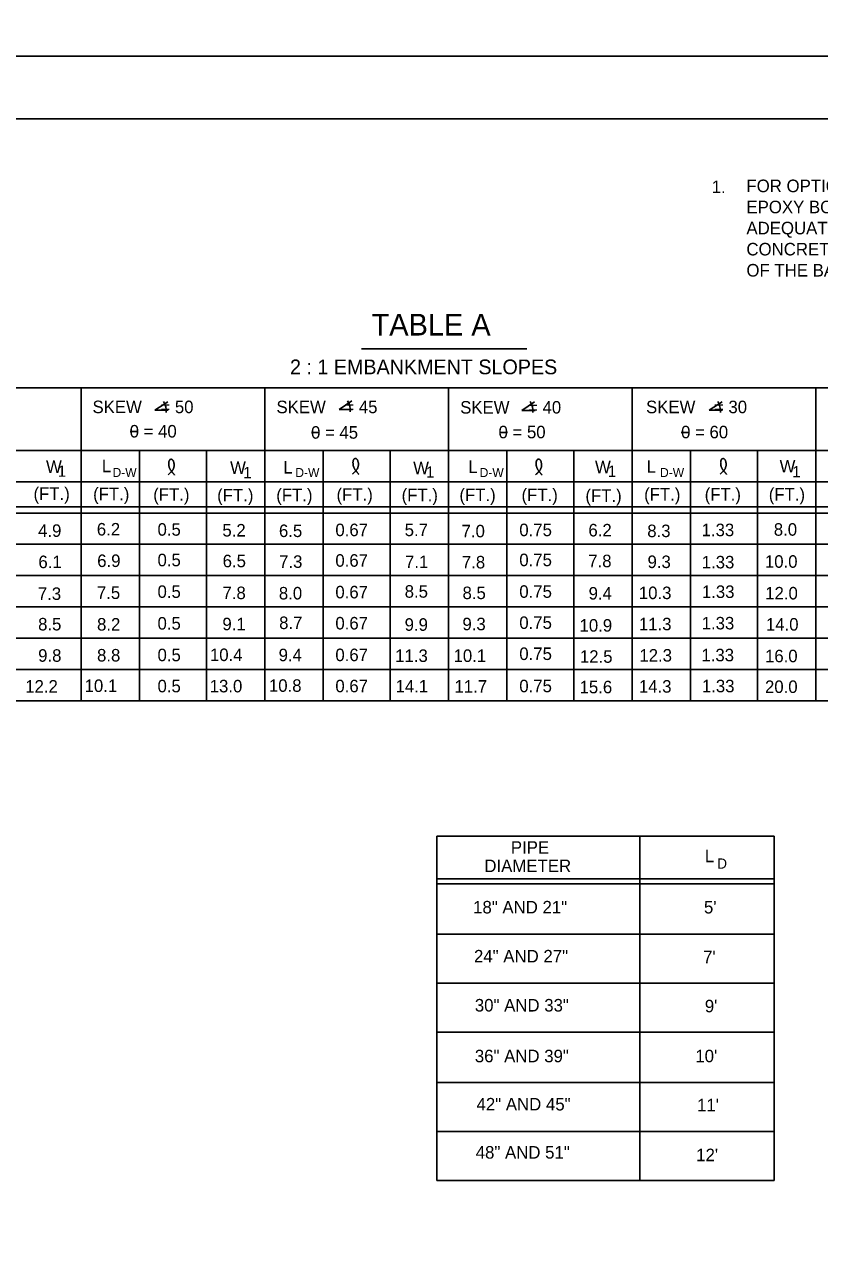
# Model space of a CAD drawing. Extents: x 638877 to 639960, y 297341 to 299123.
# Drawn here: x 639328 to 639517.9, y 297649 to 297942.8 of the extents above; entities that cross this region are included whole.
import ezdxf

# ---------------------------------------------------------------- set-up
doc = ezdxf.new("R2010")
doc.units = 0
for name, color, linetype in [('1', 7, 'Continuous'), ('2', 7, 'Continuous'), ('3', 7, 'Continuous'), ('PLT-BNDY', 7, 'Continuous')]:
    doc.layers.add(name, color=color, linetype=linetype)

msp = doc.modelspace()

# ---------------------------------------------------------------- linework, layer by layer
at = {"layer": '1'}
msp.add_line((639703.19, 297920.28), (638917.19, 297920.28), dxfattribs=at)
at = {"layer": '2'}
for p, q in [((639507.09, 297748.87), (639426.48, 297748.87)), ((639426.48, 297666.64), (639426.48, 297748.87)), ((639475.03, 297666.64), (639475.03, 297748.87)), ((639507.09, 297666.64), (639507.09, 297748.87)), ((639507.09, 297738.71), (639426.48, 297738.71)), ((639507.09, 297737.51), (639426.48, 297737.51)), ((639507.09, 297725.48), (639426.48, 297725.48)), ((639507.09, 297713.78), (639426.48, 297713.78)), ((639507.09, 297702.08), (639426.48, 297702.08)), ((639507.09, 297690.04), (639426.48, 297690.04)), ((639507.09, 297678.34), (639426.48, 297678.34)), ((639507.09, 297666.64), (639426.48, 297666.64))]:
    msp.add_line(p, q, dxfattribs=at)
at = {"layer": '3'}
for p, q in [((639408.47, 297865.33), (639448.03, 297865.33)), ((639233.8, 297856.01), (639632.75, 297856.01)), ((639341.51, 297856.01), (639341.51, 297781.21)), ((639385.4, 297856.01), (639385.4, 297781.21)), ((639429.28, 297856.01), (639429.28, 297781.21)), ((639473.17, 297856.01), (639473.17, 297781.21)), ((639517.05, 297856.01), (639517.05, 297781.21)), ((639359.13, 297850.65), (639362.21, 297852.69)), ((639403.15, 297850.84), (639406.22, 297852.88)), ((639446.79, 297850.62), (639449.86, 297852.66)), ((639491.56, 297850.65), (639494.64, 297852.69)), ((639362.34, 297850.65), (639359.13, 297850.65)), ((639406.35, 297850.84), (639403.15, 297850.84)), ((639449.99, 297850.62), (639446.79, 297850.62)), ((639494.77, 297850.65), (639491.56, 297850.65)), ((639353.21, 297845.58), (639355.15, 297845.58)), ((639396.54, 297845.29), (639398.48, 297845.29)), ((639441.44, 297845.36), (639443.38, 297845.36)), ((639484.91, 297845.36), (639486.85, 297845.36)), ((639233.8, 297841.05), (639632.75, 297841.05)), ((639355.48, 297841.05), (639355.48, 297781.21)), ((639371.44, 297841.05), (639371.44, 297781.21)), ((639399.36, 297841.05), (639399.36, 297781.21)), ((639415.32, 297841.05), (639415.32, 297781.21)), ((639443.25, 297841.05), (639443.25, 297781.21)), ((639459.21, 297841.05), (639459.21, 297781.21)), ((639487.13, 297841.05), (639487.13, 297781.21)), ((639503.09, 297841.05), (639503.09, 297781.21)), ((639233.8, 297833.57), (639632.75, 297833.57)), ((639233.8, 297827.59), (639632.75, 297827.59)), ((639233.8, 297826.09), (639632.75, 297826.09)), ((639233.8, 297818.61), (639632.75, 297818.61)), ((639233.8, 297811.13), (639632.75, 297811.13)), ((639233.8, 297803.65), (639632.75, 297803.65)), ((639233.8, 297796.17), (639632.75, 297796.17)), ((639233.8, 297788.69), (639632.75, 297788.69)), ((639233.8, 297781.21), (639632.75, 297781.21))]:
    msp.add_line(p, q, dxfattribs=at)
for centre in [(639357.76, 297850.51), (639401.77, 297850.7), (639445.41, 297850.48), (639490.19, 297850.51)]:
    msp.add_arc(centre, 4.07, 354.1715, 33.0785, dxfattribs=at)
for points in [[(639362.31, 297835.23), (639362.47, 297835.37), (639362.57, 297835.48), (639362.74, 297835.63), (639362.86, 297835.77), (639363.08, 297835.93), (639363.24, 297836.13), (639363.38, 297836.29), (639363.48, 297836.47), (639363.57, 297836.68), (639363.63, 297836.86), (639363.69, 297837.04), (639363.71, 297837.2), (639363.74, 297837.4), (639363.75, 297837.58), (639363.74, 297837.77), (639363.7, 297837.97), (639363.66, 297838.16), (639363.62, 297838.35), (639363.55, 297838.53), (639363.49, 297838.64), (639363.41, 297838.72), (639363.34, 297838.79), (639363.26, 297838.86), (639363.17, 297838.91), (639363.1, 297838.93), (639362.97, 297838.93), (639362.89, 297838.91), (639362.77, 297838.87), (639362.7, 297838.8), (639362.65, 297838.73), (639362.6, 297838.64), (639362.54, 297838.55), (639362.51, 297838.43), (639362.48, 297838.35), (639362.46, 297838.15), (639362.44, 297838.02), (639362.46, 297837.87), (639362.46, 297837.71), (639362.48, 297837.49), (639362.5, 297837.3), (639362.53, 297837.17), (639362.59, 297836.99), (639362.67, 297836.81), (639362.74, 297836.66), (639362.82, 297836.5), (639362.92, 297836.32), (639363.07, 297836.18), (639363.17, 297836.01), (639363.28, 297835.88), (639363.37, 297835.74), (639363.48, 297835.6), (639363.59, 297835.47), (639363.67, 297835.38), (639363.76, 297835.27), (639363.85, 297835.14)], [(639406.33, 297835.41), (639406.5, 297835.55), (639406.6, 297835.65), (639406.76, 297835.81), (639406.88, 297835.94), (639407.11, 297836.11), (639407.26, 297836.31), (639407.41, 297836.47), (639407.5, 297836.65), (639407.59, 297836.85), (639407.65, 297837.04), (639407.72, 297837.22), (639407.74, 297837.38), (639407.76, 297837.58), (639407.77, 297837.75), (639407.76, 297837.95), (639407.73, 297838.15), (639407.69, 297838.34), (639407.64, 297838.53), (639407.57, 297838.71), (639407.51, 297838.82), (639407.44, 297838.9), (639407.36, 297838.97), (639407.28, 297839.04), (639407.19, 297839.09), (639407.12, 297839.11), (639406.99, 297839.11), (639406.91, 297839.09), (639406.8, 297839.05), (639406.72, 297838.98), (639406.67, 297838.91), (639406.62, 297838.82), (639406.56, 297838.73), (639406.54, 297838.61), (639406.51, 297838.53), (639406.48, 297838.33), (639406.46, 297838.2), (639406.48, 297838.04), (639406.48, 297837.89), (639406.51, 297837.67), (639406.53, 297837.48), (639406.55, 297837.35), (639406.61, 297837.17), (639406.69, 297836.99), (639406.77, 297836.83), (639406.84, 297836.68), (639406.94, 297836.5), (639407.1, 297836.35), (639407.19, 297836.19), (639407.3, 297836.06), (639407.39, 297835.92), (639407.5, 297835.78), (639407.61, 297835.65), (639407.69, 297835.56), (639407.78, 297835.45), (639407.87, 297835.32)], [(639450.09, 297835.25), (639450.25, 297835.39), (639450.35, 297835.49), (639450.52, 297835.65), (639450.64, 297835.78), (639450.86, 297835.95), (639451.02, 297836.15), (639451.16, 297836.31), (639451.26, 297836.49), (639451.35, 297836.69), (639451.41, 297836.88), (639451.47, 297837.06), (639451.49, 297837.22), (639451.52, 297837.42), (639451.53, 297837.59), (639451.52, 297837.79), (639451.48, 297837.99), (639451.44, 297838.18), (639451.4, 297838.37), (639451.33, 297838.55), (639451.27, 297838.66), (639451.19, 297838.74), (639451.12, 297838.81), (639451.04, 297838.88), (639450.95, 297838.93), (639450.88, 297838.95), (639450.75, 297838.95), (639450.67, 297838.93), (639450.55, 297838.89), (639450.48, 297838.82), (639450.43, 297838.75), (639450.38, 297838.66), (639450.32, 297838.57), (639450.29, 297838.45), (639450.26, 297838.37), (639450.24, 297838.17), (639450.22, 297838.04), (639450.24, 297837.88), (639450.24, 297837.73), (639450.26, 297837.51), (639450.28, 297837.32), (639450.31, 297837.19), (639450.37, 297837.01), (639450.45, 297836.83), (639450.53, 297836.67), (639450.6, 297836.52), (639450.7, 297836.34), (639450.85, 297836.19), (639450.95, 297836.03), (639451.06, 297835.9), (639451.15, 297835.76), (639451.26, 297835.62), (639451.37, 297835.48), (639451.45, 297835.4), (639451.54, 297835.29), (639451.63, 297835.16)], [(639494.19, 297835.4), (639494.35, 297835.54), (639494.45, 297835.64), (639494.61, 297835.8), (639494.73, 297835.93), (639494.96, 297836.1), (639495.12, 297836.3), (639495.26, 297836.46), (639495.35, 297836.64), (639495.44, 297836.84), (639495.5, 297837.03), (639495.57, 297837.21), (639495.59, 297837.36), (639495.62, 297837.57), (639495.63, 297837.74), (639495.62, 297837.93), (639495.58, 297838.14), (639495.54, 297838.33), (639495.49, 297838.51), (639495.42, 297838.7), (639495.36, 297838.8), (639495.29, 297838.88), (639495.21, 297838.96), (639495.13, 297839.03), (639495.05, 297839.07), (639494.98, 297839.09), (639494.84, 297839.09), (639494.77, 297839.07), (639494.65, 297839.03), (639494.57, 297838.97), (639494.52, 297838.9), (639494.47, 297838.8), (639494.42, 297838.71), (639494.39, 297838.6), (639494.36, 297838.51), (639494.33, 297838.32), (639494.31, 297838.19), (639494.33, 297838.03), (639494.33, 297837.87), (639494.36, 297837.65), (639494.38, 297837.47), (639494.41, 297837.33), (639494.47, 297837.16), (639494.54, 297836.98), (639494.62, 297836.82), (639494.7, 297836.67), (639494.79, 297836.48), (639494.95, 297836.34), (639495.05, 297836.17), (639495.15, 297836.05), (639495.24, 297835.9), (639495.35, 297835.77), (639495.46, 297835.63), (639495.55, 297835.55), (639495.63, 297835.44), (639495.72, 297835.3)]]:
    msp.add_spline(points, degree=3, dxfattribs=at)
at = {"layer": 'PLT-BNDY'}
for points in [[(638877.19, 298529.28), (639718.19, 298529.28), (639718.19, 297935.28), (638877.19, 297935.28)], [(638877.19, 297935.28), (639718.19, 297935.28), (639718.19, 297341.28), (638877.19, 297341.28)]]:
    msp.add_lwpolyline(points, close=True, dxfattribs=at)

# ---------------------------------------------------------------- texts
at = {"layer": '1'}
for s, height, p in [('FOR OPTIONAL CONSTRUCTION JOINT WITHOUT A DEPRESSED KEY, APPLY ', 3, (639500.47, 297902.75)), ('EPOXY BONDING COMPOUND AT THE LOCATION INDICATED TO ENSURE ', 3, (639500.47, 297897.71)), ('ADEQUATE BOND WITH THE BASE SECTION OF THE ENDWALL (NEW ', 3, (639500.47, 297892.67)), ('CONCRETE). CAST THE HEADWALL SECTION OF THE ENDWALL ON TOP ', 3, (639500.47, 297887.63)), ('OF THE BASE SECTION OF THE ENDWALL.', 3, (639500.47, 297882.59)), ('D-W', 2.154, (639349.02, 297834.71)), ('D-W', 2.154, (639392.69, 297834.68)), ('D-W', 2.154, (639436.73, 297834.68)), ('D-W', 2.154, (639479.83, 297834.69)), ('D', 2.43, (639493.49, 297741.13)), ('18" AND 21"', 3, (639435.17, 297730.42)), ("5'", 3, (639490.32, 297730.42)), ('24" AND 27"', 3, (639435.38, 297718.71)), ("7'", 3, (639490.11, 297718.5)), ('30" AND 33"', 3, (639435.58, 297706.99)), ("9'", 3, (639490.53, 297706.79)), ('36" AND 39"', 3, (639435.58, 297694.86)), ("10'", 3, (639488.26, 297694.86)), ('42" AND 45"', 3, (639435.99, 297683.35)), ("11'", 3, (639488.68, 297683.15)), ('48" AND 51"', 3, (639435.79, 297671.84)), ("12'", 3, (639488.47, 297671.23))]:
    msp.add_text(s, height=height, dxfattribs=at).set_placement(p)
at = {"layer": '3'}
for s, height, p in [('1.  ', 3, (639492.17, 297902.52)), ('TABLE A', 5.172, (639410.91, 297868.5)), ('2 : 1 EMBANKMENT SLOPES', 3.5207, (639391.43, 297859.24)), ('SKEW    = 50', 2.9921, (639344.24, 297849.95)), ('SKEW    = 45', 2.9921, (639388.19, 297849.94)), ('SKEW    = 40', 2.9921, (639432.08, 297849.85)), ('SKEW    = 30', 2.9921, (639476.49, 297849.94)), ('0 = 40', 2.992, (639353.12, 297844.13)), ('0 = 45', 2.992, (639396.45, 297843.85)), ('0 = 50', 2.992, (639441.25, 297843.94)), ('0 = 60', 2.992, (639484.86, 297843.94)), ('W', 2.99, (639333.13, 297835.67)), ('1', 2.7, (639335.92, 297834.74)), ('L', 2.99, (639346.47, 297835.85)), ('W', 2.99, (639377.11, 297835.45)), ('1', 2.7, (639380.24, 297834.4)), ('L', 2.99, (639389.83, 297835.53)), ('W', 2.99, (639420.85, 297835.37)), ('1', 2.7, (639423.92, 297834.56)), ('L', 2.99, (639434.01, 297835.67)), ('W', 2.99, (639464.29, 297835.59)), ('1', 2.7, (639467.35, 297834.73)), ('L', 2.99, (639476.63, 297835.71)), ('W', 2.99, (639508.4, 297835.78)), ('1', 2.7, (639511.42, 297834.61)), ('(FT.)', 2.992, (639330.14, 297829.22)), ('(FT.)', 2.992, (639344.38, 297829.14)), ('(FT.)', 2.992, (639358.74, 297829.02)), ('(FT.)', 2.992, (639374.02, 297828.87)), ('(FT.)', 2.992, (639388.14, 297828.89)), ('(FT.)', 2.992, (639402.54, 297829.02)), ('(FT.)', 2.992, (639418.09, 297828.89)), ('(FT.)', 2.992, (639431.9, 297828.93)), ('(FT.)', 2.992, (639446.74, 297828.93)), ('(FT.)', 2.992, (639462, 297828.76)), ('(FT.)', 2.992, (639476.03, 297829.05)), ('(FT.)', 2.992, (639490.49, 297829.05)), ('(FT.)', 2.992, (639505.81, 297829.05)), ('4.9', 2.992, (639331.24, 297820.39)), ('6.2', 2.992, (639345.27, 297820.72)), ('0.5', 2.992, (639359.77, 297820.67)), ('5.2', 2.992, (639375.27, 297820.48)), ('6.5', 2.992, (639388.78, 297820.35)), ('0.67', 2.992, (639402.26, 297820.56)), ('5.7', 2.992, (639418.82, 297820.57)), ('7.0', 2.992, (639432.42, 297820.28)), ('0.75', 2.992, (639446.21, 297820.56)), ('6.2', 2.992, (639462.72, 297820.5)), ('8.3', 2.992, (639476.78, 297820.33)), ('1.33', 2.992, (639489.76, 297820.56)), ('8.0', 2.992, (639507.01, 297820.67)), ('6.9', 2.992, (639345.36, 297813.19)), ('0.5', 2.992, (639359.77, 297813.37)), ('6.5', 2.992, (639375.33, 297813.14)), ('0.67', 2.992, (639402.26, 297813.26)), ('0.75', 2.992, (639446.21, 297813.39)), ('7.8', 2.992, (639462.68, 297813.14)), ('6.1', 2.992, (639331.31, 297812.92)), ('7.3', 2.992, (639388.82, 297812.99)), ('7.1', 2.992, (639418.9, 297812.94)), ('7.8', 2.992, (639432.49, 297812.86)), ('9.3', 2.992, (639476.84, 297812.94)), ('1.33', 2.992, (639489.8, 297812.86)), ('10.0', 2.992, (639504.89, 297813.01)), ('7.3', 2.992, (639331.18, 297805.33)), ('7.5', 2.992, (639345.29, 297805.55)), ('0.5', 2.992, (639359.77, 297805.81)), ('7.8', 2.992, (639375.29, 297805.52)), ('8.0', 2.992, (639388.76, 297805.44)), ('0.67', 2.992, (639402.26, 297805.7)), ('8.5', 2.992, (639418.82, 297805.86)), ('8.5', 2.992, (639432.64, 297805.52)), ('0.75', 2.992, (639446.21, 297805.83)), ('9.4', 2.992, (639462.77, 297805.42)), ('10.3', 2.992, (639474.77, 297805.52)), ('1.33', 2.992, (639489.83, 297805.79)), ('12.0', 2.992, (639504.96, 297805.44)), ('8.7', 2.992, (639388.83, 297798.37)), ('0.75', 2.992, (639446.21, 297798.4)), ('8.5', 2.992, (639331.24, 297798.04)), ('8.2', 2.992, (639345.32, 297798)), ('0.5', 2.992, (639359.77, 297798.24)), ('9.1', 2.992, (639375.27, 297798.08)), ('0.67', 2.992, (639402.26, 297798.27)), ('9.9', 2.992, (639418.81, 297797.95)), ('9.3', 2.992, (639432.62, 297798.08)), ('10.9', 2.992, (639460.6, 297797.75)), ('11.3', 2.992, (639474.78, 297798.08)), ('1.33', 2.992, (639489.78, 297798.28)), ('14.0', 2.992, (639505.13, 297798)), ('9.8', 2.992, (639331.25, 297790.55)), ('8.8', 2.992, (639345.32, 297790.62)), ('0.5', 2.992, (639359.77, 297790.68)), ('10.4', 2.992, (639372.3, 297790.72)), ('9.4', 2.992, (639388.71, 297790.68)), ('0.67', 2.992, (639402.26, 297790.7)), ('11.3', 2.992, (639416.56, 297790.51)), ('10.1', 2.992, (639430.5, 297790.51)), ('0.75', 2.992, (639446.21, 297790.97)), ('12.5', 2.992, (639460.69, 297790.31)), ('12.3', 2.992, (639474.9, 297790.59)), ('1.33', 2.992, (639489.72, 297790.66)), ('16.0', 2.992, (639504.91, 297790.44)), ('12.2', 2.992, (639328.17, 297783.18)), ('10.1', 2.992, (639342.35, 297783.33)), ('0.5', 2.992, (639359.77, 297783.25)), ('13.0', 2.992, (639372.24, 297783.24)), ('10.8', 2.992, (639386.39, 297783.37)), ('0.67', 2.992, (639402.26, 297783.27)), ('14.1', 2.992, (639416.65, 297783.22)), ('11.7', 2.992, (639430.72, 297783.17)), ('0.75', 2.992, (639446.21, 297783.27)), ('15.6', 2.992, (639460.61, 297783.02)), ('14.3', 2.992, (639474.78, 297783.17)), ('1.33', 2.992, (639489.83, 297783.26)), ('20.0', 2.992, (639504.91, 297783.09)), ('PIPE', 3, (639444.19, 297744.69)), ('L', 3, (639490.53, 297742.66)), ('DIAMETER', 3, (639437.86, 297740.29))]:
    msp.add_text(s, height=height, dxfattribs=at).set_placement(p)

doc.saveas('drawing.dxf')
